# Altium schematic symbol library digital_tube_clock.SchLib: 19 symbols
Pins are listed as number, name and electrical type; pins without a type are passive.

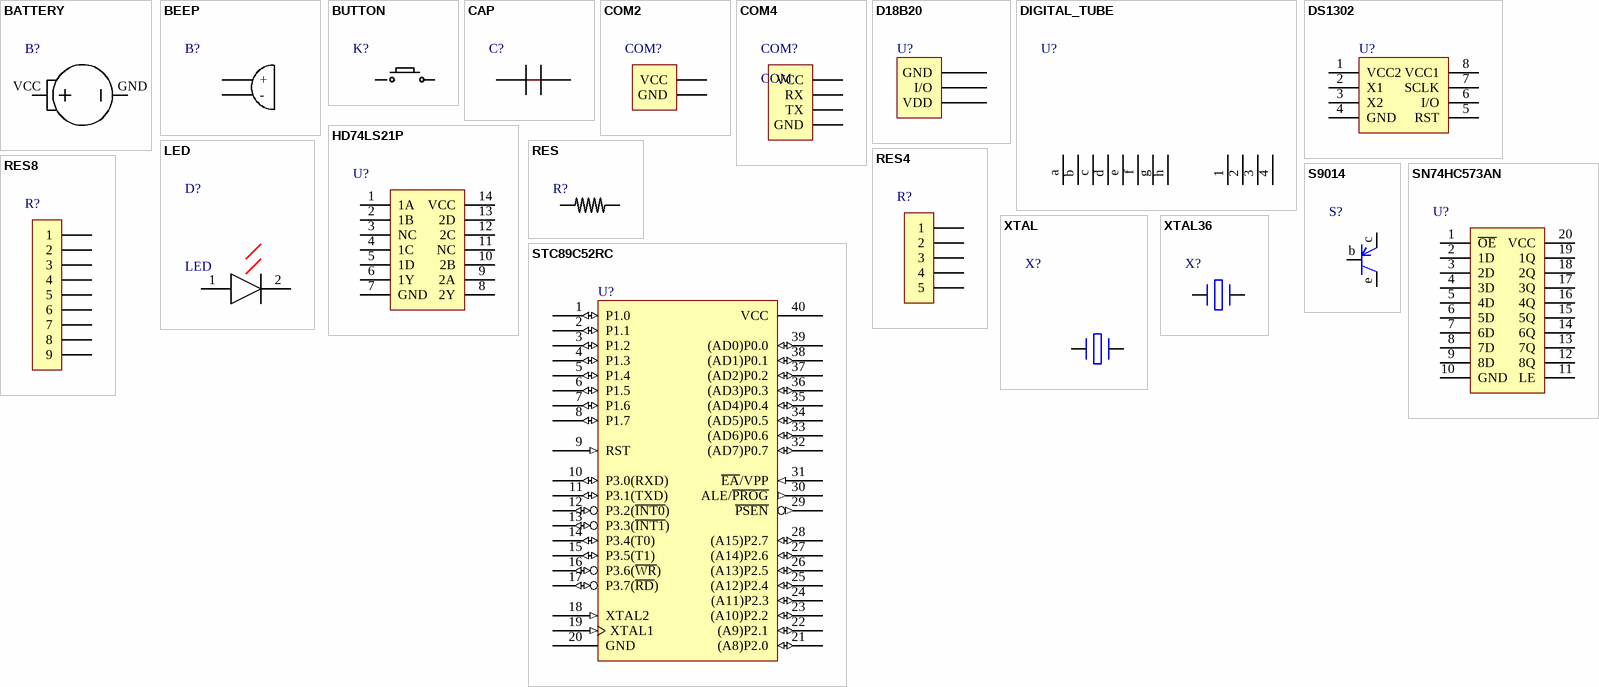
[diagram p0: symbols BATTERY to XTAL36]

## BATTERY
designator B?  (value not drawn)
footprint BAT
pins: GND, VCC

## BEEP
designator B?  (value not drawn)
footprint BEEP
pins: 1 +, 2 -

## BUTTON
designator K?  (value not drawn)
footprint BUTTON
pins: 1, 2

## CAP
designator C?  (value not drawn)
Capacitance
footprint CAP
pins: 1, 2

## COM2
designator COM?, comment COM  (value not drawn)
Power interface
footprint COM2
pins: GND, VCC

## COM4
designator COM?, comment COM
Download interface
footprint COM4
pins: GND, RX, TX, VCC

## D18B20
designator U?, comment DS18B20  (value not drawn)
Programmable Resolution  1-Wire Digital Thermometer
footprint DS18B20
pins: DQ I/O, GND, VDD

## DIGITAL_TUBE
designator U?  (value not drawn)
Dispaly panel
footprint DIGITAL (LED, 7-Segment Display, 10 mm, Three Digit; 15 Leads (4 Absent); Row Space 10.16 mm; Pitch 2.54 mm)
pins: 1, 2, 3, 4, a, b, c, d, e, f, g, h

## DS1302
designator U?  (value not drawn)
Trickle Charge Timekeeping Chip
footprint DS1302
pins: 1 VCC2, 2 X1, 3 X2, 4 GND, 5 RST, 6 I/O, 7 SCLK, 8 VCC1

## HD74LS21P
designator U?  (value not drawn)
footprint HD74LS21P
pins: 1 1A, 2 1B, 3 NC, 4 1C, 5 1D, 6 1Y, 7 GND, 8 2Y, 9 2A, 10 2B, 11 NC, 12 2C, 13 2D, 14 VCC

## LED
designator D?
The power led
footprint LED
pins: 1, 2

## RES
designator R?  (value not drawn)
Resistance
footprint RES
pins: 1, 2

## RES4
designator R?  (value not drawn)
Resistance * 4
footprint RES4
pins: 1, 2, 3, 4, 5

## RES8
designator R?  (value not drawn)
Resistance * 8
footprint RES8
pins: 1, 2, 3, 4, 5, 6, 7, 8, 9

## S9014
designator S?  (value not drawn)
footprint S9014
pins: b, c, e

## SN74HC573AN
designator U?  (value not drawn)
footprint SN74HC573AN
pins: 1 ~{OE}, 2 1D, 3 2D, 4 3D, 5 4D, 6 5D, 7 6D, 8 7D, 9 8D, 10 GND, 11 LE, 12 8Q, 13 7Q, 14 6Q, 15 5Q, 16 4Q, 17 3Q, 18 2Q, 19 1Q, 20 VCC

## STC89C52RC
designator U?  (value not drawn)
8-Bit Microcontroller with 8K ISP Flash ROM
footprint STC89C52RC
pins: 1 P1.0 (io), 2 P1.1 (io), 3 P1.2 (io), 4 P1.3 (io), 5 P1.4 (io), 6 P1.5 (io), 7 P1.6 (io), 8 P1.7 (io), 9 RST (in), 10 P3.0(RXD) (io), 11 P3.1(TXD) (io), 12 P3.2(~{INT0}) (io), 13 P3.3(~{INT1}) (io), 14 P3.4(T0) (io), 15 P3.5(T1) (io), 16 P3.6(~{WR}) (io), 17 P3.7(~{RD}) (io), 18 XTAL2 (in), 19 XTAL1 (in), 20 GND (power), 21 (A8)P2.0 (io), 22 (A9)P2.1 (io), 23 (A10)P2.2 (io), 24 (A11)P2.3 (io), 25 (A12)P2.4 (io), 26 (A13)P2.5 (io), 27 (A14)P2.6 (io), 28 (A15)P2.7 (io), 29 ~{PSEN} (out), 30 ALE/~{PROG} (out), 31 ~{EA}/VPP (in), 32 (AD7)P0.7 (io), 33 (AD6)P0.6 (io), 34 (AD5)P0.5 (io), 35 (AD4)P0.4 (io), 36 (AD3)P0.3 (io), 37 (AD2)P0.2 (io), 38 (AD1)P0.1 (io), 39 (AD0)P0.0 (io), 40 VCC (power)

## XTAL
designator X?  (value not drawn)
Generate system clock
footprint XTAL
pins: 1, 2

## XTAL36
designator X?, comment 36  (value not drawn)
footprint XTAL36
pins: 1, 2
